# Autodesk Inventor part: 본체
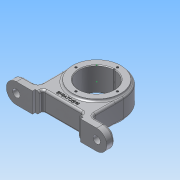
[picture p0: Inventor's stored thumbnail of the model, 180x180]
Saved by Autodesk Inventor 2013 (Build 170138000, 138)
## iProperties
Created: 2019-05
Part Number: 본체
Material: 알루미늄 6061
Document SubType Name: Modeling
Designer: Administrator
Density: 2.71 g/cm^3
Mass: 458.095 g
Surface Area: 320.639 cm^2
Volume: 169.039 cm^3
Author: Administrator
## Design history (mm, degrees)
sketch "스케치1" dims "d14" = 80
  geometry: L1 (40, -48)-(75, -48); L2 (75, -48)-(75, -60); L3 (75, -60)-(36, -60); L4 (36, -60)-(36, -56); L5 (36, -56)-(30, -56); L6 (30, -56)-(30, -50); L7 (30, -50)-(-30, -50); L8 (-30, -50)-(-30, -56); L9 (-36, -56)-(-30, -56); L10 (-36, -56)-(-36, -60); L11 (-36, -60)-(-75, -60); L12 (-75, -60)-(-75, -48); L13 (-75, -48)-(-40, -48); L14 (-40, -48)-(-40, 0); L15 (-40, 0)-(40, 0); L16 (40, -48)-(40, 0); 3 further points
  constraints: 32 end point, 12 perpendicular, 3 parallel, 2 coincident, 2 horizontal alignment, 1 horizontal, 1 midpoint, 1 vertical, 2 other
  dimensions: "d3" = 60 distance between parallel lines of L11 L15; "d7" = 4 distance between parallel lines of L9 L11; "d9" = 4 distance between parallel lines of L3 L5; "d11" = 12 distance between parallel lines of L11 L13; "d12" = 12 distance between parallel lines of L3 L1; "d18" = 10 distance from line of L10.end L7; "d20" = 150 distance of L2.end L11.end; "d21" = 39 distance of L2.end L3.end; "d22" = 39 distance of L10.end L11.end; "d23" = 60 distance of L5.end L8.end; "d24" = 75 horizontal distance of point (0, 0) L11.end; "d26" = 6 distance of L9.start L8.end
extrude "돌출1" new body sketch "스케치1" stored distance "d27" = 30; taper "d28" = 0 deg
sketch "스케치3"
  geometry: 1 further point
sketch "스케치4"
  geometry: C1 r 36 at (0, 0); 1 further point
  constraints: 1 centre point, 1 coincident
  dimensions: "d32" = 36 radius of C1
extrude "돌출2" join sketch "스케치4" stored distance "d33" = 36; taper "d34" = 0 deg
sketch "스케치5"
  geometry: C1 r 26 at (0, 0); 1 further point
  constraints: 1 centre point, 1 coincident
  dimensions: "d35" = 26 radius of C1
extrude "돌출3" cut sketch "스케치5" distance "d36" = 36; taper "d37" = 0 deg
sketch "스케치6"
  geometry: C1 r 9 at (20, 15); 1 further point
  constraints: 1 centre point, 1 horizontal alignment
  dimensions: "d39" = 9 radius of C1; "d40" = 60 distance of C1.centre point (-40, 15)
extrude "돌출4" join sketch "스케치6" distance "d41" = 3; taper "d42" = 0 deg
sketch "스케치7"
  geometry: L1 (-100, 15)-(-20, 15) reference; L2 (-20, 15)-(-20, -15) reference; L3 (-20, -15)-(-100, -15) reference; L4 (-100, -15)-(-100, 15) reference; C1 r 9 at (-120, 0) reference; C2 r 9 at (0, 0) reference; C3 r 5.5 at (0, 0); 1 further point
  constraints: 1 centre point, 1 coincident
  dimensions: "d43" = 5.5 radius of C3
extrude "돌출5" cut sketch "스케치7" distance "d44" = 111; taper "d45" = 0 deg
sketch "스케치8" dims "d47" = 31
  geometry: 3 further points
  constraints: 2 vertical alignment, 1 coincident, 2 other
hole "구멍1" sketch "스케치8" at (0, 31) diameter "d49" = 3.242; stored, may be unused: countersink angle "d53" = 90 deg, drill point angle "d55" = 118 deg; dims "d50" = 6, "d51" = 4, "d52" = 2, "d54" = 8
sketch "스케치9"
  geometry: C1 r 1.621 at (31, 0) reference; C2 r 1.621 at (0, -31) reference; C3 r 1.621 at (-31, 0) reference; C4 r 1.621 at (0, 31) reference; C5 r 36 at (0, 0) reference; C6 r 1.5 at (0, 26); 2 further points
  constraints: 2 vertical alignment, 1 centre point, 1 other
  dimensions: "d59" = 3 diameter of C6
extrude "돌출6" cut sketch "스케치9" distance "d62" = 111; taper "d63" = 0 deg
node "작업 평면1"
sketch "스케치10"
  geometry: L1 (0, -15)-(0, 15) reference; 2 further points
  constraints: 1 coincident
hole "구멍2" sketch "스케치10" at (0, 0) diameter "d65" = 4.917; stored, may be unused: countersink angle "d69" = 90 deg, drill point angle "d71" = 118 deg; dims "d66" = 8, "d67" = 7, "d68" = 1, "d70" = 10
sketch "스케치11"
  geometry: C1 r 1 at (0, 0); 1 further point
  constraints: 1 centre point, 1 coincident
  dimensions: "d74" = 1 radius of C1
extrude "돌출7" cut sketch "스케치11" distance "d75" = 50; taper "d76" = 0 deg
fillet "모깎기2" dims "d77" = 6
chamfer "모따기1" distance "d78" = 1; stored, may be unused: second distance "d79" = 2, angle "d80" = 45 deg
fillet "모깎기4" dims "d82" = 3
fillet "모깎기5" dims "d83" = 3
fillet "모깎기6" dims "d84" = 15
fillet "모깎기7" dims "d85" = 3
fillet "모깎기8" dims "d86" = 3
node "작업 평면2"
sketch "스케치12"
  geometry: 1 further point
sketch "스케치13"
  geometry: L1 (-30, -50)-(30, -50) reference; 3 further points
  constraints: 1 vertical alignment, 1 other
  dimensions: "d89" = 7 distance from line of L1 point (0, -43)
feature "엠보싱1" sketch "스케치13" dims "d3" = 60, "d7" = 4, "d9" = 4, "d11" = 12, "d12" = 12, "d14" = 80, "d18" = 10, "d20" = 150, "d21" = 39, "d22" = 39, "d23" = 60, "d24" = 75, "d26" = 6, "d91" = 0.5, "d92" = 0
fillet "모깎기10" dims "d93" = 3
fillet "모깎기11" dims "d94" = 3
node "솔리드1"
mirror "대칭1"
mirror "대칭2"
pattern_circular "원형 패턴1" dims angle "d57" = 360 deg
mirror "대칭3"
node "절단 모서리 투영1"
node "절단 모서리 투영2"
node "절단 모서리 투영3"
other parameters: "d87" = 36.5
